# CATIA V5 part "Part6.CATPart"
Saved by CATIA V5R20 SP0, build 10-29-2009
Part number: 9CS061215
Revision: ANY
Definition: UNKNOWN
Nomenclature: 9CS061215
Source: Unknown
Bounding box of the stored display mesh (mm): x -5.85 to 5.85, y 0 to 15, z -6 to 6
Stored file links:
  C:\Users\Utente\Desktop\IO LAVORO\3D X SITO CF\CUMSA\3D files PW\pw060830\pw060830_injection\Part6.CATPart
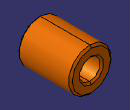
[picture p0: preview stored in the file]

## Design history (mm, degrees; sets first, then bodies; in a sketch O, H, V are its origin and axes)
Body1 "Revolución1" (main body)
  Solid1: solid without history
